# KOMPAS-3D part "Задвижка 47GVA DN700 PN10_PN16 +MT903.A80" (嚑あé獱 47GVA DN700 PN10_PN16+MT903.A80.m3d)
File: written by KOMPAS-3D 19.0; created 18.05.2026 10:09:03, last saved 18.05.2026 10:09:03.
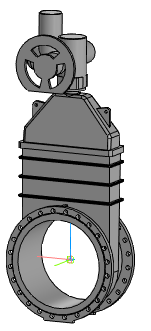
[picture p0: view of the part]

Document properties: Автор: Энергия; Полное имя файла: ..\Задвижка 47GVA DN40_DN1000+MT903.A\Задвижка 47GVA DN700 PN10_PN16+MT903.A801.a3d

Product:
- Part/product: Задвижка 47GVA DN700 PN10_PN16 +MT903.A80
    Масса: 1699.06
  - Body: Электропривод МТ903.А80 без блока управления
      Масса: 346.451
  - Body: Задвижка 47GVA DN700 PN10_PN16_F16 без исполнительного механизма
      Масса: 1352.61

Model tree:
1. Операция без истории:1
2. Операция без истории:2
